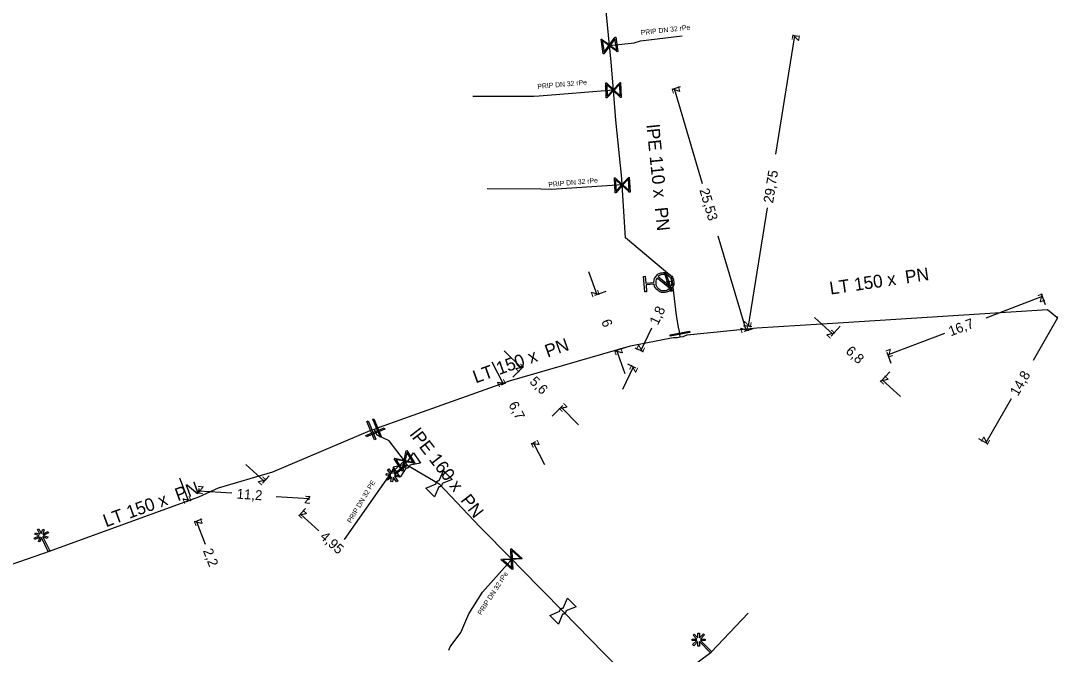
# Model space of a CAD drawing. Extents: x -643842 to -636370, y -1119190 to -1110210.
# Drawn here: x -640965.7 to -640861.5, y -1114718.7 to -1114654.6 of the extents above; entities that cross this region are included whole.
import ezdxf

# ---------------------------------------------------------------- set-up
doc = ezdxf.new("R2010")
doc.units = 0
for name, color, linetype in [('2', 7, 'Continuous'), ('22', 7, 'Continuous'), ('Default', 7, 'Continuous'), ('Level 10', 7, 'Continuous'), ('Level 16', 7, 'Continuous'), ('Level 20', 7, 'Continuous'), ('Level 21', 7, 'Continuous'), ('Level 23', 7, 'Continuous'), ('Level 28', 7, 'Continuous'), ('Level 33', 7, 'Continuous')]:
    doc.layers.add(name, color=color, linetype=linetype)

msp = doc.modelspace()

# ---------------------------------------------------------------- linework, layer by layer
at = {"layer": '2'}
for points in [[(-640928.18, -1114700.8), (-640928.61, -1114701.12), (-640928.7, -1114700.99), (-640928.27, -1114700.68), (-640928.74, -1114700.61), (-640928.71, -1114700.45), (-640928.25, -1114700.52), (-640928.59, -1114700.06), (-640928.47, -1114699.96), (-640928.12, -1114700.44), (-640928.05, -1114699.97), (-640927.89, -1114699.99), (-640927.96, -1114700.45), (-640926.69, -1114699.52), (-640926.6, -1114699.64), (-640927.88, -1114700.58), (-640927.41, -1114700.65), (-640927.43, -1114700.81), (-640927.9, -1114700.73), (-640927.56, -1114701.21), (-640927.68, -1114701.3), (-640928.02, -1114700.83), (-640928.09, -1114701.29), (-640928.25, -1114701.27), (-640928.18, -1114700.8)], [(-640963.78, -1114706.59), (-640964.02, -1114706.11), (-640963.88, -1114706.04), (-640963.64, -1114706.52), (-640963.49, -1114706.08), (-640963.34, -1114706.13), (-640963.49, -1114706.57), (-640962.97, -1114706.31), (-640962.91, -1114706.45), (-640963.43, -1114706.71), (-640962.98, -1114706.86), (-640963.03, -1114707.01), (-640963.47, -1114706.86), (-640962.78, -1114708.28), (-640962.92, -1114708.35), (-640963.62, -1114706.93), (-640963.77, -1114707.37), (-640963.92, -1114707.32), (-640963.76, -1114706.87), (-640964.29, -1114707.13), (-640964.36, -1114706.99), (-640963.84, -1114706.74), (-640964.28, -1114706.59), (-640964.23, -1114706.44), (-640963.78, -1114706.59)], [(-640897.3, -1114717.19), (-640897.68, -1114716.8), (-640897.57, -1114716.69), (-640897.19, -1114717.07), (-640897.19, -1114716.6), (-640897.03, -1114716.6), (-640897.03, -1114717.07), (-640896.63, -1114716.66), (-640896.52, -1114716.77), (-640896.93, -1114717.19), (-640896.46, -1114717.19), (-640896.46, -1114717.34), (-640896.92, -1114717.34), (-640895.8, -1114718.46), (-640895.91, -1114718.57), (-640897.03, -1114717.45), (-640897.03, -1114717.92), (-640897.19, -1114717.92), (-640897.19, -1114717.45), (-640897.61, -1114717.86), (-640897.72, -1114717.75), (-640897.31, -1114717.34), (-640897.77, -1114717.34), (-640897.77, -1114717.19), (-640897.3, -1114717.19)]]:
    msp.add_lwpolyline(points, dxfattribs=at)
at = {"layer": 'Default'}
for points in [[(-640901.64, -1114681.12), (-640901.64, -1114680.76), (-640901.4, -1114680.48), (-640901.14, -1114680.17), (-640900.72, -1114680.13), (-640900.31, -1114680.1), (-640899.99, -1114680.37), (-640899.68, -1114680.63), (-640899.64, -1114681.05), (-640899.61, -1114681.46), (-640899.88, -1114681.78), (-640900.14, -1114682.09), (-640900.55, -1114682.13), (-640900.97, -1114682.16), (-640901.29, -1114681.9), (-640901.57, -1114681.66), (-640901.62, -1114681.3)], [(-640899.96, -1114681.58), (-640899.81, -1114681.35), (-640899.83, -1114681.06), (-640899.86, -1114680.73), (-640900.12, -1114680.51), (-640900.37, -1114680.29), (-640900.71, -1114680.32), (-640901, -1114680.35), (-640901.2, -1114680.54)], [(-640901.32, -1114680.68), (-640901.48, -1114680.91), (-640901.45, -1114681.2), (-640901.42, -1114681.54), (-640901.17, -1114681.75), (-640900.91, -1114681.97), (-640900.57, -1114681.94), (-640900.28, -1114681.92), (-640900.08, -1114681.72)], [(-640926.95, -1114699.55), (-640926.95, -1114699.49), (-640926.92, -1114699.45), (-640926.88, -1114699.37), (-640926.82, -1114699.32), (-640926.75, -1114699.28), (-640926.67, -1114699.27), (-640926.61, -1114699.26), (-640926.56, -1114699.28)], [(-640926.33, -1114699.61), (-640926.33, -1114699.67), (-640926.36, -1114699.72), (-640926.4, -1114699.79), (-640926.46, -1114699.84), (-640926.53, -1114699.88), (-640926.62, -1114699.89), (-640926.67, -1114699.9), (-640926.72, -1114699.88)], [(-640923.69, -1114701.5), (-640923.7, -1114701.45), (-640923.68, -1114701.4), (-640923.66, -1114701.32), (-640923.6, -1114701.26), (-640923.54, -1114701.2), (-640923.46, -1114701.18), (-640923.41, -1114701.16), (-640923.36, -1114701.17)], [(-640923.07, -1114701.46), (-640923.06, -1114701.51), (-640923.08, -1114701.56), (-640923.1, -1114701.64), (-640923.16, -1114701.7), (-640923.22, -1114701.76), (-640923.3, -1114701.78), (-640923.35, -1114701.8), (-640923.41, -1114701.79)], [(-640911.16, -1114714.38), (-640911.17, -1114714.33), (-640911.15, -1114714.28), (-640911.13, -1114714.2), (-640911.07, -1114714.14), (-640911.01, -1114714.08), (-640910.93, -1114714.06), (-640910.88, -1114714.04), (-640910.83, -1114714.05)], [(-640910.54, -1114714.34), (-640910.53, -1114714.39), (-640910.55, -1114714.44), (-640910.57, -1114714.52), (-640910.63, -1114714.58), (-640910.69, -1114714.64), (-640910.77, -1114714.66), (-640910.82, -1114714.68), (-640910.88, -1114714.67)]]:
    msp.add_open_spline(points, degree=3, dxfattribs=at)
at = {"layer": 'Level 10'}
for points in [[(-640889.3, -1114668.16), (-640887.38, -1114656.18)], [(-640887.01, -1114656.24), (-640887.63, -1114656.14)], [(-640898.97, -1114661.36), (-640899.81, -1114661.61)], [(-640896.71, -1114671.15), (-640899.57, -1114661.54)], [(-640890.17, -1114673.58), (-640892.09, -1114685.56)], [(-640895.16, -1114676.4), (-640892.3, -1114686.01)], [(-640908.25, -1114680.01), (-640907.41, -1114682.36)], [(-640906.51, -1114682.04), (-640907.64, -1114682.44)], [(-640862.01, -1114683.38), (-640862.42, -1114682.29)], [(-640868.03, -1114684.69), (-640862.33, -1114682.53)], [(-640863.24, -1114688.97), (-640860.67, -1114684.51)], [(-640891.72, -1114685.62), (-640892.33, -1114685.52)], [(-640885.38, -1114684.68), (-640883.54, -1114686.37)], [(-640882.79, -1114685.55), (-640883.71, -1114686.56)], [(-640901.9, -1114685.75), (-640902.96, -1114688.01)], [(-640891.71, -1114685.84), (-640892.54, -1114686.09)], [(-640872.24, -1114686.29), (-640877.94, -1114688.46)], [(-640904.49, -1114687.69), (-640905.62, -1114688.09)], [(-640916.79, -1114688.05), (-640915.01, -1114689.81)], [(-640904.54, -1114690.36), (-640905.39, -1114688.01)], [(-640903.57, -1114687.73), (-640902.73, -1114688.12)], [(-640877.62, -1114689.31), (-640878.03, -1114688.22)], [(-640918.03, -1114689.17), (-640916.89, -1114691.39)], [(-640915.91, -1114690.71), (-640914.84, -1114689.63)], [(-640904.78, -1114691.91), (-640903.72, -1114689.65)], [(-640904.33, -1114689.36), (-640903.49, -1114689.75)], [(-640877.78, -1114690.15), (-640878.7, -1114691.16)], [(-640916.7, -1114691.3), (-640917.11, -1114691.51)], [(-640876.69, -1114692.66), (-640878.53, -1114690.97)], [(-640865.49, -1114692.88), (-640868.06, -1114697.34)], [(-640911.93, -1114694.65), (-640910.86, -1114693.57)], [(-640909.26, -1114695.51), (-640911.03, -1114693.75)], [(-640868.79, -1114696.92), (-640867.85, -1114697.46)], [(-640913.64, -1114697.26), (-640914.05, -1114697.47)], [(-640912.69, -1114699.58), (-640913.83, -1114697.35)], [(-640942.92, -1114699.55), (-640941.07, -1114701.23)], [(-640949.64, -1114700.9), (-640948.72, -1114703.23)], [(-640940.57, -1114700.67), (-640941.24, -1114701.41)], [(-640947.7, -1114702.34), (-640947.67, -1114701.97)], [(-640944.35, -1114702.45), (-640947.69, -1114702.22)], [(-640948.2, -1114703.02), (-640948.96, -1114703.32)], [(-640939.85, -1114702.76), (-640936.52, -1114702.99)], [(-640936.53, -1114703.12), (-640936.5, -1114702.74)], [(-640936.9, -1114703.99), (-640937.57, -1114704.73)], [(-640947.4, -1114705.07), (-640948.15, -1114705.37)], [(-640947.01, -1114707.61), (-640947.92, -1114705.28)], [(-640935.55, -1114706.23), (-640937.4, -1114704.55)]]:
    msp.add_lwpolyline(points, dxfattribs=at)
at = {"layer": 'Level 16'}
for points in [[(-640905.51, -1114656.31), (-640905.28, -1114657.79), (-640905.35, -1114657.8), (-640905.45, -1114657.72), (-640906.13, -1114657.22), (-640906.7, -1114658), (-640906.76, -1114658.01), (-640906.99, -1114656.53), (-640906.93, -1114656.52), (-640906.14, -1114657.1), (-640905.65, -1114656.42), (-640905.57, -1114656.32), (-640905.51, -1114656.31)], [(-640906.69, -1114657.85), (-640906.2, -1114657.17), (-640906.87, -1114656.67), (-640906.69, -1114657.85)], [(-640905.58, -1114656.48), (-640906.07, -1114657.15), (-640905.4, -1114657.65), (-640905.58, -1114656.48)], [(-640905.01, -1114660.91), (-640904.97, -1114662.41), (-640905.03, -1114662.41), (-640905.13, -1114662.32), (-640905.73, -1114661.74), (-640906.4, -1114662.45), (-640906.47, -1114662.45), (-640906.51, -1114660.95), (-640906.44, -1114660.95), (-640905.74, -1114661.62), (-640905.16, -1114661.01), (-640905.07, -1114660.91), (-640905.01, -1114660.91)], [(-640906.38, -1114662.29), (-640905.8, -1114661.68), (-640906.41, -1114661.1), (-640906.38, -1114662.29)], [(-640905.1, -1114661.07), (-640905.67, -1114661.68), (-640905.07, -1114662.25), (-640905.1, -1114661.07)], [(-640904.13, -1114670.49), (-640904.06, -1114671.99), (-640904.13, -1114671.99), (-640904.22, -1114671.9), (-640904.84, -1114671.34), (-640905.5, -1114672.05), (-640905.56, -1114672.06), (-640905.63, -1114670.56), (-640905.56, -1114670.55), (-640904.85, -1114671.21), (-640904.28, -1114670.59), (-640904.19, -1114670.5), (-640904.13, -1114670.49)], [(-640905.48, -1114671.9), (-640904.91, -1114671.28), (-640905.53, -1114670.71), (-640905.48, -1114671.9)], [(-640904.22, -1114670.65), (-640904.78, -1114671.27), (-640904.16, -1114671.84), (-640904.22, -1114670.65)], [(-640899.92, -1114682.05), (-640900.57, -1114680.15), (-640900.46, -1114680.11), (-640899.81, -1114682.01), (-640899.92, -1114682.05)], [(-640898.02, -1114686.18), (-640899.99, -1114686.56), (-640900.01, -1114686.44), (-640898.05, -1114686.06), (-640898.02, -1114686.18)], [(-640929.97, -1114694.91), (-640929.19, -1114696.76), (-640929.31, -1114696.81), (-640930.09, -1114694.96), (-640929.97, -1114694.91)], [(-640928.88, -1114695.95), (-640930.73, -1114696.73), (-640930.78, -1114696.61), (-640928.93, -1114695.83), (-640928.88, -1114695.95)], [(-640930.57, -1114695.13), (-640929.79, -1114696.98), (-640929.91, -1114697.03), (-640930.69, -1114695.18), (-640930.57, -1114695.13)], [(-640926.65, -1114698.13), (-640925.83, -1114699.39), (-640925.89, -1114699.43), (-640926.01, -1114699.4), (-640926.83, -1114699.22), (-640927.04, -1114700.17), (-640927.09, -1114700.21), (-640927.91, -1114698.95), (-640927.85, -1114698.91), (-640926.9, -1114699.12), (-640926.73, -1114698.3), (-640926.7, -1114698.17), (-640926.65, -1114698.13)], [(-640927.1, -1114700.03), (-640926.92, -1114699.2), (-640927.74, -1114699.03), (-640927.1, -1114700.03)], [(-640926.64, -1114698.32), (-640926.82, -1114699.14), (-640926, -1114699.31), (-640926.64, -1114698.32)], [(-640916.09, -1114708.04), (-640914.97, -1114709.04), (-640915.01, -1114709.09), (-640915.14, -1114709.09), (-640915.98, -1114709.14), (-640915.93, -1114710.11), (-640915.97, -1114710.16), (-640917.09, -1114709.16), (-640917.05, -1114709.11), (-640916.07, -1114709.06), (-640916.12, -1114708.22), (-640916.13, -1114708.09), (-640916.09, -1114708.04)], [(-640916.03, -1114708.22), (-640915.99, -1114709.05), (-640915.15, -1114709.01), (-640916.03, -1114708.22)], [(-640916.02, -1114709.99), (-640916.07, -1114709.15), (-640916.91, -1114709.19), (-640916.02, -1114709.99)]]:
    msp.add_lwpolyline(points, dxfattribs=at)
at = {"layer": 'Level 21'}
for points in [[(-640898.97, -1114686.61), (-640899.01, -1114686.34), (-640899.02, -1114686.31), (-640899.06, -1114686.09), (-640899.14, -1114685.65), (-640899.36, -1114684.46), (-640899.76, -1114681.03), (-640899.83, -1114680.57), (-640904.5, -1114676.6), (-640904.85, -1114671.27), (-640904.89, -1114670.61), (-640905.49, -1114664.71), (-640905.74, -1114661.68), (-640905.97, -1114658.82), (-640906.14, -1114657.16), (-640906.55, -1114653), (-640907.16, -1114646.88), (-640907.58, -1114642.75), (-640907.66, -1114641.9), (-640907.75, -1114641), (-640907.84, -1114639.08)], [(-640929.4, -1114695.76), (-640916.26, -1114691.07), (-640904.02, -1114687.52), (-640899.7, -1114686.7), (-640899.24, -1114686.71), (-640898.97, -1114686.61), (-640898.69, -1114686.58), (-640898.27, -1114686.44), (-640891.23, -1114685.7), (-640882.45, -1114685.18), (-640861.83, -1114683.85), (-640853.83, -1114690.43), (-640853.64, -1114690.62)], [(-640929.91, -1114695.98), (-640930.24, -1114696.08), (-640930.4, -1114696.14)], [(-640929.4, -1114695.76), (-640929.64, -1114695.86), (-640929.91, -1114695.98)], [(-640926.64, -1114699.58), (-640926.87, -1114699.17), (-640928.43, -1114697.15), (-640929.66, -1114696.57), (-640929.83, -1114696.28), (-640929.91, -1114695.98)], [(-640930.4, -1114696.14), (-640940.23, -1114700.3), (-640945.74, -1114701.94), (-640947.73, -1114702.84), (-640962.85, -1114708.32)], [(-640926.64, -1114699.58), (-640923.38, -1114701.48), (-640919.24, -1114705.85), (-640916.03, -1114709.1), (-640915.05, -1114710.12), (-640910.85, -1114714.36), (-640906.69, -1114718.64), (-640902.45, -1114722.81)], [(-640962.85, -1114708.32), (-640965.05, -1114709.11), (-640970.55, -1114710.99), (-640976.17, -1114713), (-640982.27, -1114715.45)]]:
    msp.add_lwpolyline(points, dxfattribs=at)
at = {"layer": 'Level 23'}
for points in [[(-640906.14, -1114657.16), (-640903.65, -1114656.91), (-640902.99, -1114656.68), (-640898.77, -1114656.2)], [(-640905.74, -1114661.68), (-640913.24, -1114662.29), (-640913.8, -1114662.34), (-640919.96, -1114662.34)], [(-640904.85, -1114671.27), (-640912, -1114671.74), (-640913.1, -1114671.68), (-640918.52, -1114671.65)], [(-640899.76, -1114681.03), (-640900.19, -1114681.08), (-640900.64, -1114681.13)], [(-640926.87, -1114699.17), (-640928.31, -1114700.45), (-640932.98, -1114707.12)], [(-640922.4, -1114718.32), (-640922.25, -1114717.99), (-640921.17, -1114716.53), (-640920.37, -1114714.62), (-640918.97, -1114712.46), (-640916.19, -1114709.31), (-640916.03, -1114709.1)], [(-640895.86, -1114718.52), (-640892.1, -1114714.58)], [(-640901.44, -1114723.81), (-640898.61, -1114720.57), (-640895.86, -1114718.52)]]:
    msp.add_lwpolyline(points, dxfattribs=at)
at = {"layer": 'Level 28'}
for points in [[(-640926.56, -1114699.28), (-640925.96, -1114698.36), (-640925.26, -1114699.39), (-640926.33, -1114699.61)], [(-640927.32, -1114700.8), (-640928.02, -1114699.77), (-640926.95, -1114699.55)], [(-640926.72, -1114699.88), (-640927.32, -1114700.8)], [(-640923.36, -1114701.17), (-640922.93, -1114700.16), (-640922.05, -1114701.04), (-640923.07, -1114701.46)], [(-640923.83, -1114702.8), (-640924.71, -1114701.92), (-640923.69, -1114701.5)], [(-640923.41, -1114701.79), (-640923.83, -1114702.8)], [(-640910.83, -1114714.05), (-640910.4, -1114713.04), (-640909.52, -1114713.92), (-640910.54, -1114714.34)], [(-640911.3, -1114715.68), (-640912.18, -1114714.8), (-640911.16, -1114714.38)], [(-640910.88, -1114714.67), (-640911.3, -1114715.68)]]:
    msp.add_lwpolyline(points, dxfattribs=at)
at = {"layer": 'Level 33'}
for points in [[(-640901.62, -1114681.3), (-640902.44, -1114681.37), (-640902.38, -1114682.06), (-640902.57, -1114682.08), (-640902.7, -1114680.52), (-640902.52, -1114680.5), (-640902.46, -1114681.19), (-640901.64, -1114681.12)], [(-640900.08, -1114681.72), (-640901.32, -1114680.68)], [(-640901.2, -1114680.54), (-640899.96, -1114681.58)]]:
    msp.add_lwpolyline(points, dxfattribs=at)

# ---------------------------------------------------------------- texts
at = {"layer": '22'}
for s, rotation, p in [('PRIP DN 32 rPe', 6.4444, (-640902.94, -1114656.12)), ('PRIP DN 32 rPe', 5.1022, (-640913.41, -1114661.56)), ('PRIP DN 32 rPe', 5.1022, (-640912.3, -1114671.48)), ('PRIP DN 32 PE', 59.048, (-640932.3, -1114705.5)), ('PRIP DN 32 rPe', 57.0508, (-640919.11, -1114714.8))]:
    msp.add_text(s, height=0.5, rotation=rotation, dxfattribs=at).set_placement(p)
at = {"layer": 'Level 10'}
for s, rotation, p in [('z', 80.8957, (-640886.96, -1114656.76)), ('z', 106.5273, (-640898.95, -1114661.88)), ('29,75', 80.8957, (-640889.59, -1114673.16)), ('25,53', 286.5273, (-640897.05, -1114671.77)), ('z', 289.6915, (-640908.05, -1114682.06)), ('z', 20.8082, (-640862.62, -1114683.17)), ('1,8', 64.9641, (-640901.24, -1114685.51)), ('6', 289.6915, (-640906.98, -1114685.05)), ('z', 286.5273, (-640892.93, -1114685.68)), ('z', 260.8957, (-640892.5, -1114684.98)), ('16,7', 20.8082, (-640871.6, -1114686.58)), ('z', 317.427, (-640884.25, -1114686.4)), ('z', 244.9641, (-640903.2, -1114687.35)), ('6,8', 317.427, (-640882.31, -1114688.18)), ('z', 109.6915, (-640904.75, -1114688.31)), ('z', 200.8082, (-640877.65, -1114687.81)), ('z', 315.2664, (-640915.72, -1114689.81)), ('z', 64.9641, (-640903.48, -1114690.31)), ('5,6', 315.2664, (-640914.29, -1114691.23)), ('z', 137.427, (-640877.83, -1114690.94)), ('14,8', 60.0414, (-640864.81, -1114692.69)), ('z', 297.1578, (-640917.56, -1114691.18)), ('6,7', 297.1578, (-640916.38, -1114693.47)), ('z', 135.2664, (-640910.33, -1114693.75)), ('z', 117.1578, (-640913.16, -1114697.57)), ('z', 240.0414, (-640868.25, -1114696.65)), ('z', 317.8466, (-640941.78, -1114701.26)), ('z', 176.0155, (-640947.16, -1114701.75)), ('11,2', 356.0155, (-640943.89, -1114702.98)), ('z', 291.4056, (-640949.37, -1114702.95)), ('z', 356.0155, (-640937.05, -1114703.46)), ('z', 137.8466, (-640936.69, -1114704.51)), ('z', 111.4056, (-640947.27, -1114705.56)), ('4,95', 317.8466, (-640935.51, -1114706.93)), ('2,2', 291.4056, (-640947.29, -1114708.25))]:
    msp.add_text(s, height=1, rotation=rotation, dxfattribs=at).set_placement(p)
at = {"layer": 'Level 20'}
for s, rotation, p in [('lPE 110 x  PN ', 275.8067, (-640902.4, -1114665.21)), ('LT 150 x  PN ', 8.3997, (-640883.77, -1114682.36)), ('LT 150 x  PN ', 19.6454, (-640919.68, -1114691.34)), ('lPE 160 x  PN ', 307.6781, (-640926.41, -1114696.51)), ('LT 150 x  PN ', 19.9199, (-640957.09, -1114705.89))]:
    msp.add_text(s, height=1.3, rotation=rotation, dxfattribs=at).set_placement(p)

doc.saveas('drawing.dxf')
